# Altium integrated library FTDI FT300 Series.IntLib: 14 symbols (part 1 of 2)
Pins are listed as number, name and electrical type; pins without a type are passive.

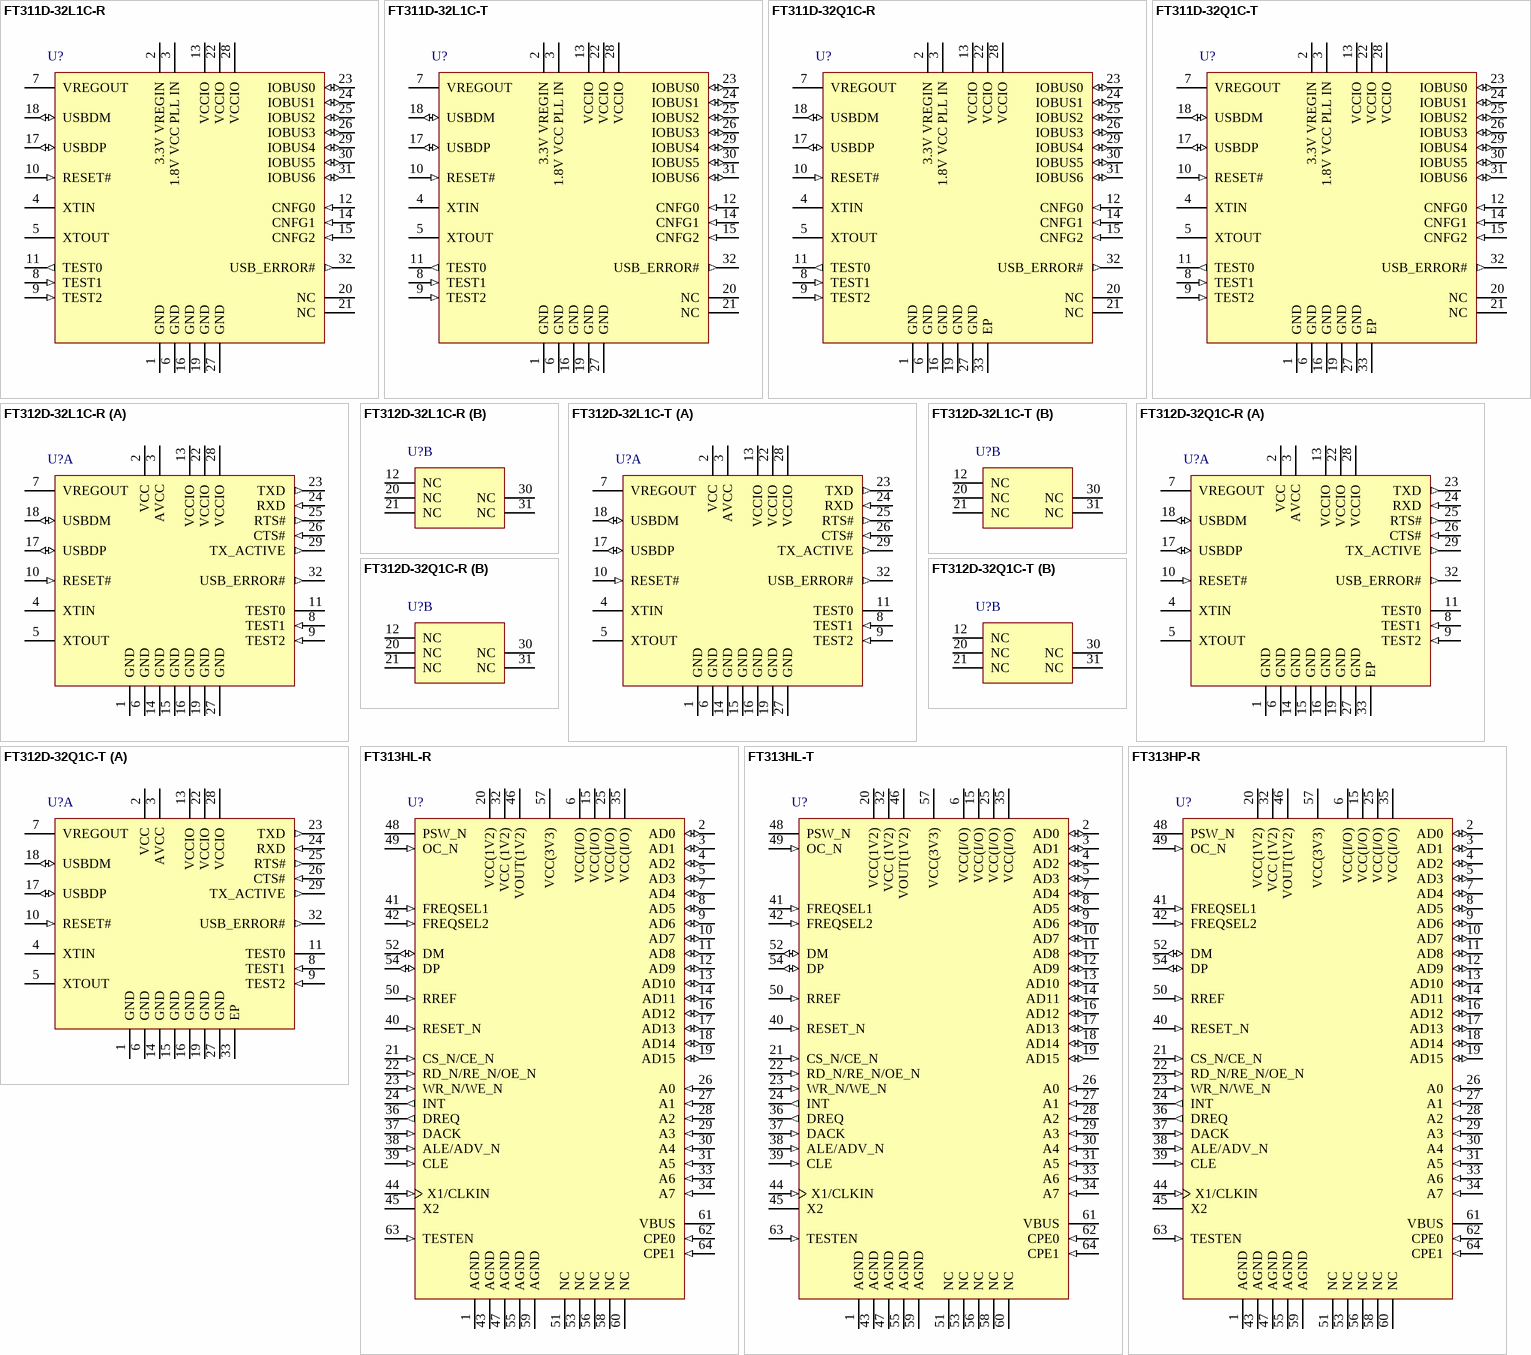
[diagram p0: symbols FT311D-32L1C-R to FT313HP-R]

## FT311D-32L1C-R
designator U?
FT311D Single Chip USB Android Host IC, -40 to +85 degC, 32-pin LQFP, Pb-Free, Tape and Reel; Manufacturer: FTDI; PartNumber: FT311D-32L1C-R
footprint LQFP-32_N (Thin QFP, 32-Leads, Body 7x7mm, Pitch 0.8mm, IPC Medium Density)
footprint LQFP-32_L (Thin QFP, 32-Leads, Body 7x7mm, Pitch 0.8mm, IPC High Density)
footprint LQFP-32_M (Thin QFP, 32-Leads, Body 7x7mm, Pitch 0.8mm, IPC Low Density)
pins: 1 GND (power) "0V Ground input.", 2 3.3V VREGIN (power) "3V3 supply to IC internal 1V8 regulator", 3 1.8V VCC PLL IN (power) "1V8 supply to IC core", 4 XTIN "Input to 12MHz Oscillator Cell. Connect 12MHz crystal across pins 4 and 5.", 5 XTOUT "Output from 12MHz Oscillator Cell. Connect 12MHz crystal across pins 4 and 5.", 6 GND (power) "0V Ground input.", 7 VREGOUT (power) "1V8 output. May be used as input source for pin 3.", 8 TEST1 (in) "For internal use. Pull to GND", 9 TEST2 (in) "For factory use. Pull to 3V3.", 10 RESET# (in) "Reset input (active low).", 11 TEST0 (out) "Active low signal that may be used to control a switch for enabling power to the USB port pin 1 (VBUS).", 12 CNFG0 (in) "Configuration pin 0 used to select between GPIO,UART,PWM,I2C and SPI. Pull to Ground = Logic '0'(No external resistor needed) Leave Open = Logic '1' (Internal Pull up is present)", 13 VCCIO (power) "3V3 supply for the IO cells", 14 CNFG1 (in) "Configuration pin 1 used to select between GPIO,UART,PWM,I2C and SPI. Pull to Ground = Logic '0'(No external resistor needed) Leave Open = Logic '1' (Internal Pull up is present)", 15 CNFG2 (in) "Configuration pin 2 used to select between GPIO,UART,PWM,I2C and SPI. Pull to Ground = Logic '0'(No external resistor needed) Leave Open = Logic '1' (Internal Pull up is present)", 16 GND (power) "0V Ground input.", 17 USBDP (io) "USB Data Signal Plus.", 18 USBDM (io) "USB Data Signal Minus.", 19 GND (power) "0V Ground input.", 20 NC "No connect pins. Leave unterminated.", 21 NC "No connect pins. Leave unterminated.", 22 VCCIO (power) "3V3 supply for the IO cells", 23 IOBUS0 (io) "I/O signal. Function depends on CNFG pin setting.", 24 IOBUS1 (io) "I/O signal. Function depends on CNFG pin setting.", 25 IOBUS2 (io) "I/O signal. Function depends on CNFG pin setting.", 26 IOBUS3 (io) "I/O signal. Function depends on CNFG pin setting.", 27 GND (power) "0V Ground input.", 28 VCCIO (power) "3V3 supply for the IO cells", 29 IOBUS4 (io) "I/O signal. Function depends on CNFG pin setting.", 30 IOBUS5 (io) "I/O signal. Function depends on CNFG pin setting.", 31 IOBUS6 (io) "I/O signal. Function depends on CNFG pin setting.", 32 USB_ERROR# (out) "Output signal to indicate a problem with the USB connection"

## FT311D-32L1C-T
designator U?
FT311D Single Chip USB Android Host IC, -40 to +85 degC, 32-pin LQFP, Pb-Free, Tray; Manufacturer: FTDI; PartNumber: FT311D-32L1C-T
footprint LQFP-32_N (Thin QFP, 32-Leads, Body 7x7mm, Pitch 0.8mm, IPC Medium Density)
footprint LQFP-32_L (Thin QFP, 32-Leads, Body 7x7mm, Pitch 0.8mm, IPC High Density)
footprint LQFP-32_M (Thin QFP, 32-Leads, Body 7x7mm, Pitch 0.8mm, IPC Low Density)
pins: 1 GND (power) "0V Ground input.", 2 3.3V VREGIN (power) "3V3 supply to IC internal 1V8 regulator", 3 1.8V VCC PLL IN (power) "1V8 supply to IC core", 4 XTIN "Input to 12MHz Oscillator Cell. Connect 12MHz crystal across pins 4 and 5.", 5 XTOUT "Output from 12MHz Oscillator Cell. Connect 12MHz crystal across pins 4 and 5.", 6 GND (power) "0V Ground input.", 7 VREGOUT (power) "1V8 output. May be used as input source for pin 3.", 8 TEST1 (in) "For internal use. Pull to GND", 9 TEST2 (in) "For factory use. Pull to 3V3.", 10 RESET# (in) "Reset input (active low).", 11 TEST0 (out) "Active low signal that may be used to control a switch for enabling power to the USB port pin 1 (VBUS).", 12 CNFG0 (in) "Configuration pin 0 used to select between GPIO,UART,PWM,I2C and SPI. Pull to Ground = Logic '0'(No external resistor needed) Leave Open = Logic '1' (Internal Pull up is present)", 13 VCCIO (power) "3V3 supply for the IO cells", 14 CNFG1 (in) "Configuration pin 1 used to select between GPIO,UART,PWM,I2C and SPI. Pull to Ground = Logic '0'(No external resistor needed) Leave Open = Logic '1' (Internal Pull up is present)", 15 CNFG2 (in) "Configuration pin 2 used to select between GPIO,UART,PWM,I2C and SPI. Pull to Ground = Logic '0'(No external resistor needed) Leave Open = Logic '1' (Internal Pull up is present)", 16 GND (power) "0V Ground input.", 17 USBDP (io) "USB Data Signal Plus.", 18 USBDM (io) "USB Data Signal Minus.", 19 GND (power) "0V Ground input.", 20 NC "No connect pins. Leave unterminated.", 21 NC "No connect pins. Leave unterminated.", 22 VCCIO (power) "3V3 supply for the IO cells", 23 IOBUS0 (io) "I/O signal. Function depends on CNFG pin setting.", 24 IOBUS1 (io) "I/O signal. Function depends on CNFG pin setting.", 25 IOBUS2 (io) "I/O signal. Function depends on CNFG pin setting.", 26 IOBUS3 (io) "I/O signal. Function depends on CNFG pin setting.", 27 GND (power) "0V Ground input.", 28 VCCIO (power) "3V3 supply for the IO cells", 29 IOBUS4 (io) "I/O signal. Function depends on CNFG pin setting.", 30 IOBUS5 (io) "I/O signal. Function depends on CNFG pin setting.", 31 IOBUS6 (io) "I/O signal. Function depends on CNFG pin setting.", 32 USB_ERROR# (out) "Output signal to indicate a problem with the USB connection"

## FT311D-32Q1C-R
designator U?
FT311D Single Chip USB Android Host IC, -40 to +85 degC, 32-pin QFN, Pb-Free, Tape and Reel; Manufacturer: FTDI; PartNumber: FT311D-32Q1C-R
footprint QFN7X7-32_N (QFN, 32-Leads, Body 7x7mm, Pitch 0.65mm, Thermal Pad 4.8x4.8mm, IPC Medium Density)
footprint QFN7X7-32_L (QFN, 32-Leads, Body 7x7mm, Pitch 0.65mm, Thermal Pad 4.8x4.8mm, IPC High Density)
footprint QFN7X7-32_M (QFN, 32-Leads, Body 7x7mm, Pitch 0.65mm, Thermal Pad 4.8x4.8mm, IPC Low Density)
pins: 1 GND (power) "0V Ground input.", 2 3.3V VREGIN (power) "3V3 supply to IC internal 1V8 regulator", 3 1.8V VCC PLL IN (power) "1V8 supply to IC core", 4 XTIN "Input to 12MHz Oscillator Cell. Connect 12MHz crystal across pins 4 and 5.", 5 XTOUT "Output from 12MHz Oscillator Cell. Connect 12MHz crystal across pins 4 and 5.", 6 GND (power) "0V Ground input.", 7 VREGOUT (power) "1V8 output. May be used as input source for pin 3.", 8 TEST1 (in) "For internal use. Pull to GND", 9 TEST2 (in) "For factory use. Pull to 3V3.", 10 RESET# (in) "Reset input (active low).", 11 TEST0 (out) "Active low signal that may be used to control a switch for enabling power to the USB port pin 1 (VBUS).", 12 CNFG0 (in) "Configuration pin 0 used to select between GPIO,UART,PWM,I2C and SPI. Pull to Ground = Logic '0'(No external resistor needed) Leave Open = Logic '1' (Internal Pull up is present)", 13 VCCIO (power) "3V3 supply for the IO cells", 14 CNFG1 (in) "Configuration pin 1 used to select between GPIO,UART,PWM,I2C and SPI. Pull to Ground = Logic '0'(No external resistor needed) Leave Open = Logic '1' (Internal Pull up is present)", 15 CNFG2 (in) "Configuration pin 2 used to select between GPIO,UART,PWM,I2C and SPI. Pull to Ground = Logic '0'(No external resistor needed) Leave Open = Logic '1' (Internal Pull up is present)", 16 GND (power) "0V Ground input.", 17 USBDP (io) "USB Data Signal Plus.", 18 USBDM (io) "USB Data Signal Minus.", 19 GND (power) "0V Ground input.", 20 NC "No connect pins. Leave unterminated.", 21 NC "No connect pins. Leave unterminated.", 22 VCCIO (power) "3V3 supply for the IO cells", 23 IOBUS0 (io) "I/O signal. Function depends on CNFG pin setting.", 24 IOBUS1 (io) "I/O signal. Function depends on CNFG pin setting.", 25 IOBUS2 (io) "I/O signal. Function depends on CNFG pin setting.", 26 IOBUS3 (io) "I/O signal. Function depends on CNFG pin setting.", 27 GND (power) "0V Ground input.", 28 VCCIO (power) "3V3 supply for the IO cells", 29 IOBUS4 (io) "I/O signal. Function depends on CNFG pin setting.", 30 IOBUS5 (io) "I/O signal. Function depends on CNFG pin setting.", 31 IOBUS6 (io) "I/O signal. Function depends on CNFG pin setting.", 32 USB_ERROR# (out) "Output signal to indicate a problem with the USB connection", 33 EP (power) "The centre pad should be connected to the GND plane for improved thermal conduction and noise immunity."

## FT311D-32Q1C-T
designator U?
FT311D Single Chip USB Android Host IC, -40 to +85 degC, 32-pin QFN, Pb-Free, Tray; Manufacturer: FTDI; PartNumber: FT311D-32Q1C-T
footprint QFN7X7-32_N (QFN, 32-Leads, Body 7x7mm, Pitch 0.65mm, Thermal Pad 4.8x4.8mm, IPC Medium Density)
footprint QFN7X7-32_L (QFN, 32-Leads, Body 7x7mm, Pitch 0.65mm, Thermal Pad 4.8x4.8mm, IPC High Density)
footprint QFN7X7-32_M (QFN, 32-Leads, Body 7x7mm, Pitch 0.65mm, Thermal Pad 4.8x4.8mm, IPC Low Density)
pins: 1 GND (power) "0V Ground input.", 2 3.3V VREGIN (power) "3V3 supply to IC internal 1V8 regulator", 3 1.8V VCC PLL IN (power) "1V8 supply to IC core", 4 XTIN "Input to 12MHz Oscillator Cell. Connect 12MHz crystal across pins 4 and 5.", 5 XTOUT "Output from 12MHz Oscillator Cell. Connect 12MHz crystal across pins 4 and 5.", 6 GND (power) "0V Ground input.", 7 VREGOUT (power) "1V8 output. May be used as input source for pin 3.", 8 TEST1 (in) "For internal use. Pull to GND", 9 TEST2 (in) "For factory use. Pull to 3V3.", 10 RESET# (in) "Reset input (active low).", 11 TEST0 (out) "Active low signal that may be used to control a switch for enabling power to the USB port pin 1 (VBUS).", 12 CNFG0 (in) "Configuration pin 0 used to select between GPIO,UART,PWM,I2C and SPI. Pull to Ground = Logic '0'(No external resistor needed) Leave Open = Logic '1' (Internal Pull up is present)", 13 VCCIO (power) "3V3 supply for the IO cells", 14 CNFG1 (in) "Configuration pin 1 used to select between GPIO,UART,PWM,I2C and SPI. Pull to Ground = Logic '0'(No external resistor needed) Leave Open = Logic '1' (Internal Pull up is present)", 15 CNFG2 (in) "Configuration pin 2 used to select between GPIO,UART,PWM,I2C and SPI. Pull to Ground = Logic '0'(No external resistor needed) Leave Open = Logic '1' (Internal Pull up is present)", 16 GND (power) "0V Ground input.", 17 USBDP (io) "USB Data Signal Plus.", 18 USBDM (io) "USB Data Signal Minus.", 19 GND (power) "0V Ground input.", 20 NC "No connect pins. Leave unterminated.", 21 NC "No connect pins. Leave unterminated.", 22 VCCIO (power) "3V3 supply for the IO cells", 23 IOBUS0 (io) "I/O signal. Function depends on CNFG pin setting.", 24 IOBUS1 (io) "I/O signal. Function depends on CNFG pin setting.", 25 IOBUS2 (io) "I/O signal. Function depends on CNFG pin setting.", 26 IOBUS3 (io) "I/O signal. Function depends on CNFG pin setting.", 27 GND (power) "0V Ground input.", 28 VCCIO (power) "3V3 supply for the IO cells", 29 IOBUS4 (io) "I/O signal. Function depends on CNFG pin setting.", 30 IOBUS5 (io) "I/O signal. Function depends on CNFG pin setting.", 31 IOBUS6 (io) "I/O signal. Function depends on CNFG pin setting.", 32 USB_ERROR# (out) "Output signal to indicate a problem with the USB connection", 33 EP (power) "The centre pad should be connected to the GND plane for improved thermal conduction and noise immunity."

## FT312D-32L1C-R
designator U?
FT312D Single Chip USB Android Host IC, -40 to +85 degC, 32-pin LQFP, Pb-Free, Tape and Reel; Manufacturer: FTDI; PartNumber: FT312D-32L1C-R
footprint LQFP-32_N (Thin QFP, 32-Leads, Body 7x7mm, Pitch 0.8mm, IPC Medium Density)
footprint LQFP-32_L (Thin QFP, 32-Leads, Body 7x7mm, Pitch 0.8mm, IPC High Density)
footprint LQFP-32_M (Thin QFP, 32-Leads, Body 7x7mm, Pitch 0.8mm, IPC Low Density)
part A pins: 1 GND (power) "0V Ground input.", 2 VCC (power) "3V3 supply to IC internal 1V8 regulator", 3 AVCC (power) "1V8 supply to IC core", 4 XTIN "Input to 12MHz Oscillator Cell. Connect 12MHz crystal across pins 4 and 5.", 5 XTOUT "Output from 12MHz Oscillator Cell. Connect 12MHz crystal across pins 4 and 5.", 6 GND (power) "0V Ground input.", 7 VREGOUT (power) "1V8 output. May be used as input source for pin 3.", 8 TEST1 (in) "For internal use. Pull to GND", 9 TEST2 (in) "For factory use. Pull to 3V3.", 10 RESET# (in) "Reset input (active low).", 11 TEST0 "Leave unterminated.", 13 VCCIO (power) "3V3 supply for the IO cells", 14 GND (power) "0V Ground input.", 15 GND (power) "0V Ground input.", 16 GND (power) "0V Ground input.", 17 USBDP (io) "USB Data Signal Plus.", 18 USBDM (io) "USB Data Signal Minus.", 19 GND (power) "0V Ground input.", 22 VCCIO (power) "3V3 supply for the IO cells", 23 TXD (out) "Transmit asynchronous data output", 24 RXD (in) "Receive asynchronous data input", 25 RTS# (out) "Request to send control output", 26 CTS# (in) "Clear to send control input", 27 GND (power) "0V Ground input.", 28 VCCIO (power) "3V3 supply for the IO cells", 29 TX_ACTIVE (out) "UART active signal (typically used with RS485)", 32 USB_ERROR# (out) "Output signal to indicate a problem with the USB connection"
part B pins: 12 NC "No connect pins. Leave unterminated.", 20 NC "No connect pins. Leave unterminated.", 21 NC "No connect pins. Leave unterminated.", 30 NC "No connect pins. Leave un-terminated", 31 NC "No connect pins. Leave un-terminated"

## FT312D-32L1C-T
designator U?
FT312D Single Chip USB Android Host IC, -40 to +85 degC, 32-pin LQFP, Pb-Free, Tray; Manufacturer: FTDI; PartNumber: FT312D-32L1C-T
footprint LQFP-32_N (Thin QFP, 32-Leads, Body 7x7mm, Pitch 0.8mm, IPC Medium Density)
footprint LQFP-32_L (Thin QFP, 32-Leads, Body 7x7mm, Pitch 0.8mm, IPC High Density)
footprint LQFP-32_M (Thin QFP, 32-Leads, Body 7x7mm, Pitch 0.8mm, IPC Low Density)
part A pins: 1 GND (power) "0V Ground input.", 2 VCC (power) "3V3 supply to IC internal 1V8 regulator", 3 AVCC (power) "1V8 supply to IC core", 4 XTIN "Input to 12MHz Oscillator Cell. Connect 12MHz crystal across pins 4 and 5.", 5 XTOUT "Output from 12MHz Oscillator Cell. Connect 12MHz crystal across pins 4 and 5.", 6 GND (power) "0V Ground input.", 7 VREGOUT (power) "1V8 output. May be used as input source for pin 3.", 8 TEST1 (in) "For internal use. Pull to GND", 9 TEST2 (in) "For factory use. Pull to 3V3.", 10 RESET# (in) "Reset input (active low).", 11 TEST0 "Leave unterminated.", 13 VCCIO (power) "3V3 supply for the IO cells", 14 GND (power) "0V Ground input.", 15 GND (power) "0V Ground input.", 16 GND (power) "0V Ground input.", 17 USBDP (io) "USB Data Signal Plus.", 18 USBDM (io) "USB Data Signal Minus.", 19 GND (power) "0V Ground input.", 22 VCCIO (power) "3V3 supply for the IO cells", 23 TXD (out) "Transmit asynchronous data output", 24 RXD (in) "Receive asynchronous data input", 25 RTS# (out) "Request to send control output", 26 CTS# (in) "Clear to send control input", 27 GND (power) "0V Ground input.", 28 VCCIO (power) "3V3 supply for the IO cells", 29 TX_ACTIVE (out) "UART active signal (typically used with RS485)", 32 USB_ERROR# (out) "Output signal to indicate a problem with the USB connection"
part B pins: 12 NC "No connect pins. Leave unterminated.", 20 NC "No connect pins. Leave unterminated.", 21 NC "No connect pins. Leave unterminated.", 30 NC "No connect pins. Leave un-terminated", 31 NC "No connect pins. Leave un-terminated"

## FT312D-32Q1C-R
designator U?
FT312D Single Chip USB Android Host IC, -40 to +85 degC, 32-pin QFN, Pb-Free, Tape and Reel; Manufacturer: FTDI; PartNumber: FT312D-32Q1C-R
footprint QFN7X7-32_N (QFN, 32-Leads, Body 7x7mm, Pitch 0.65mm, Thermal Pad 4.8x4.8mm, IPC Medium Density)
footprint QFN7X7-32_L (QFN, 32-Leads, Body 7x7mm, Pitch 0.65mm, Thermal Pad 4.8x4.8mm, IPC High Density)
footprint QFN7X7-32_M (QFN, 32-Leads, Body 7x7mm, Pitch 0.65mm, Thermal Pad 4.8x4.8mm, IPC Low Density)
part A pins: 1 GND (power) "0V Ground input.", 2 VCC (power) "3V3 supply to IC internal 1V8 regulator", 3 AVCC (power) "1V8 supply to IC core", 4 XTIN "Input to 12MHz Oscillator Cell. Connect 12MHz crystal across pins 4 and 5.", 5 XTOUT "Output from 12MHz Oscillator Cell. Connect 12MHz crystal across pins 4 and 5.", 6 GND (power) "0V Ground input.", 7 VREGOUT (power) "1V8 output. May be used as input source for pin 3.", 8 TEST1 (in) "For internal use. Pull to GND", 9 TEST2 (in) "For factory use. Pull to 3V3.", 10 RESET# (in) "Reset input (active low).", 11 TEST0 "Leave unterminated.", 13 VCCIO (power) "3V3 supply for the IO cells", 14 GND (power) "0V Ground input.", 15 GND (power) "0V Ground input.", 16 GND (power) "0V Ground input.", 17 USBDP (io) "USB Data Signal Plus.", 18 USBDM (io) "USB Data Signal Minus.", 19 GND (power) "0V Ground input.", 22 VCCIO (power) "3V3 supply for the IO cells", 23 TXD (out) "Transmit asynchronous data output", 24 RXD (in) "Receive asynchronous data input", 25 RTS# (out) "Request to send control output", 26 CTS# (in) "Clear to send control input", 27 GND (power) "0V Ground input.", 28 VCCIO (power) "3V3 supply for the IO cells", 29 TX_ACTIVE (out) "UART active signal (typically used with RS485)", 32 USB_ERROR# (out) "Output signal to indicate a problem with the USB connection", 33 EP (power) "The centre pad should be connected to the GND plane for improved thermal conduction and noise immunity."
part B pins: 12 NC "No connect pins. Leave unterminated.", 20 NC "No connect pins. Leave unterminated.", 21 NC "No connect pins. Leave unterminated.", 30 NC "No connect pins. Leave un-terminated", 31 NC "No connect pins. Leave un-terminated"

## FT312D-32Q1C-T
designator U?
FT312D Single Chip USB Android Host IC, -40 to +85 degC, 32-pin QFN, Pb-Free, Tray; Manufacturer: FTDI; PartNumber: FT312D-32Q1C-T
footprint QFN7X7-32_N (QFN, 32-Leads, Body 7x7mm, Pitch 0.65mm, Thermal Pad 4.8x4.8mm, IPC Medium Density)
footprint QFN7X7-32_L (QFN, 32-Leads, Body 7x7mm, Pitch 0.65mm, Thermal Pad 4.8x4.8mm, IPC High Density)
footprint QFN7X7-32_M (QFN, 32-Leads, Body 7x7mm, Pitch 0.65mm, Thermal Pad 4.8x4.8mm, IPC Low Density)
part A pins: 1 GND (power) "0V Ground input.", 2 VCC (power) "3V3 supply to IC internal 1V8 regulator", 3 AVCC (power) "1V8 supply to IC core", 4 XTIN "Input to 12MHz Oscillator Cell. Connect 12MHz crystal across pins 4 and 5.", 5 XTOUT "Output from 12MHz Oscillator Cell. Connect 12MHz crystal across pins 4 and 5.", 6 GND (power) "0V Ground input.", 7 VREGOUT (power) "1V8 output. May be used as input source for pin 3.", 8 TEST1 (in) "For internal use. Pull to GND", 9 TEST2 (in) "For factory use. Pull to 3V3.", 10 RESET# (in) "Reset input (active low).", 11 TEST0 "Leave unterminated.", 13 VCCIO (power) "3V3 supply for the IO cells", 14 GND (power) "0V Ground input.", 15 GND (power) "0V Ground input.", 16 GND (power) "0V Ground input.", 17 USBDP (io) "USB Data Signal Plus.", 18 USBDM (io) "USB Data Signal Minus.", 19 GND (power) "0V Ground input.", 22 VCCIO (power) "3V3 supply for the IO cells", 23 TXD (out) "Transmit asynchronous data output", 24 RXD (in) "Receive asynchronous data input", 25 RTS# (out) "Request to send control output", 26 CTS# (in) "Clear to send control input", 27 GND (power) "0V Ground input.", 28 VCCIO (power) "3V3 supply for the IO cells", 29 TX_ACTIVE (out) "UART active signal (typically used with RS485)", 32 USB_ERROR# (out) "Output signal to indicate a problem with the USB connection", 33 EP (power) "The centre pad should be connected to the GND plane for improved thermal conduction and noise immunity."
part B pins: 12 NC "No connect pins. Leave unterminated.", 20 NC "No connect pins. Leave unterminated.", 21 NC "No connect pins. Leave unterminated.", 30 NC "No connect pins. Leave un-terminated", 31 NC "No connect pins. Leave un-terminated"

## FT313HL-R
designator U?
FT313H Single Chip USB2.0 HS Embedded Host Controller, -40 to +85 degC, 64-pin LQFP, Pb-Free, Tape and Reel; Manufacturer: FTDI; PartNumber: FT313HL-R
footprint LQFP-64_N (Thin QFP, 64-Leads, Body 10x10mm, Pitch 0.5mm, IPC Medium Density)
footprint LQFP-64_L (Thin QFP, 64-Leads, Body 10x10mm, Pitch 0.5mm, IPC High Density)
footprint LQFP-64_M (Thin QFP, 64-Leads, Body 10x10mm, Pitch 0.5mm, IPC Low Density)
pins: 1 AGND (power) "Analog Ground", 2 AD0 (io) "Bit 0 of the address and data bus. Bidirectional pad; push-pull, three-state output. 3.3V tolerant", 3 AD1 (io) "Bit 1 of the address and data bus. Bidirectional pad; push-pull, three-state output. 3.3V tolerant", 4 AD2 (io) "Bit 2 of the address and data bus. Bidirectional pad; push-pull, three-state output. 3.3V tolerant", 5 AD3 (io) "Bit 3 of the address and data bus. Bidirectional pad; push-pull, three-state output. 3.3V tolerant", 6 VCC(I/O) (power) "I/O supply voltage; connect a 0.1uF decoupling capacitor. 1.8V, 2.5V or 3.3V", 7 AD4 (io) "Bit 4 of the address and data bus. Bidirectional pad; push-pull, three-state output. 3.3V tolerant", 8 AD5 (io) "Bit 5 of the address and data bus. Bidirectional pad; push-pull, three-state output. 3.3V tolerant", 9 AD6 (io) "Bit 6 of the address and data bus. Bidirectional pad; push-pull, three-state output. 3.3V tolerant", 10 AD7 (io) "Bit 7 of the address and data bus. Bidirectional pad; push-pull, three-state output. 3.3V tolerant", 11 AD8 (io) "Bit 8 of the address and data bus. Bidirectional pad; push-pull, three-state output. 3.3V tolerant", 12 AD9 (io) "Bit 9 of the address and data bus. Bidirectional pad; push-pull, three-state output. 3.3V tolerant", 13 AD10 (io) "Bit 10 of the address and data bus. Bidirectional pad; push-pull, three-state output. 3.3V tolerant", 14 AD11 (io) "Bit 11 of the address and data bus. Bidirectional pad; push-pull, three-state output. 3.3V tolerant", 15 VCC(I/O) (power) "I/O supply voltage; connect a 0.1uF decoupling capacitor. 1.8V, 2.5V or 3.3V", 16 AD12 (io) "Bit 12 of the address and data bus. Bidirectional pad; push-pull, three-state output. 3.3V tolerant", 17 AD13 (io) "Bit 13 of the address and data bus. Bidirectional pad; push-pull, three-state output. 3.3V tolerant", 18 AD14 (io) "Bit 14 of the address and data bus. Bidirectional pad; push-pull, three-state output. 3.3V tolerant", 19 AD15 (io) "Bit 15 of the address and data bus. Bidirectional pad; push-pull, three-state output. 3.3V tolerant", 20 VCC(1V2) (power) "Core power 1.2V input; for normal operation, this pin must be connected to pin 46. Connect a 0.1uF decoupling capacitor", 21 CS_N/CE_N (in), 22 RD_N/RE_N/OE_N (in), 23 WR_N/WE_N (in), 24 INT (out) "Interrupt output. Push-pull output; 3.3V tolerant", 25 VCC(I/O) (power) "I/O supply voltage; connect a 0.1uF decoupling capacitor. 1.8V, 2.5V or 3.3V", 26 A0 (in) "Bit 0 of the address bus; when not in use, connect to GND. Input; 3.3V tolerant", 27 A1 (in) "Bit 1 of the address bus; when not in use, connect to GND. Input; 3.3V tolerant", 28 A2 (in) "Bit 2 of the address bus; when not in use, connect to GND. Input; 3.3V tolerant", 29 A3 (in) "Bit 3 of the address bus; when not in use, connect to GND. Input; 3.3V tolerant", 30 A4 (in) "Bit 4 of the address bus; when not in use, connect to GND. Input; 3.3V tolerant", 31 A5 (in) "Bit 5 of the address bus; when not in use, connect to GND. Input; 3.3V tolerant", 32 VCC (1V2) (power) "Core power 1.2V input; for normal operation, this pin must be connected to pin 46. Connect a 0.1uF decoupling capacitor.", 33 A6 (in) "Bit 6 of the address bus; when not in use, connect to GND. Input; 3.3V tolerant", 34 A7 (in) "Bit 7 of the address bus; when not in use, connect to GND. Input; 3.3V tolerant", 35 VCC(I/O) (power) "I/O supply voltage; connect a 0.1uF decoupling capacitor. 1.8V, 2.5V or 3.3V", 36 DREQ (out) "DMA request; Push-pull output; 3.3V tolerant", 37 DACK (in) "DMA acknowledge; Internal pull-down. Input; 3.3V tolerant", 38 ALE/ADV_N (in), 39 CLE (in) "Command latch enable. Input; 3.3V tolerant", 40 RESET_N (in) "Chip reset; Internal pull-up. Input; 3.3V tolerant", 41 FREQSEL1 (in) "Input clock frequency selection pin1. Input; 3.3V tolerant", 42 FREQSEL2 (in) "Input clock frequency selection pin2. Input; 3.3V tolerant", 43 AGND (power) "Analog Ground", 44 X1/CLKIN (in) "Crystal oscillator or clock input; 3.3V peak input allowed", 45 X2 "Crystal oscillator output; leave open if an external clock is applied on pin X1/CLKIN", 46 VOUT(1V2) (power) "Internal 1.2V regulator output; connect 4.7uF and 0.1uF decoupling capacitors to this pin.", 47 AGND (power) "Analog Ground", 48 PSW_N (oc) "Port power switch; when not in use, connect to VCC(3V3) through a 10kOhm resistor. Open drain output; 5V tolerant", 49 OC_N (in) "Over current input; when not in use, connect to VCC(3V3) through a 10KOhm resistor. Input; 5V tolerant", 50 RREF (in) "Port reference resistor connection. Connect 12 kOhm±1% resistor between RREF and GND", 51 NC "No connect", 52 DM (io) "Port DM; connect to the D- pin of the USB connector", 53 NC "No connect", 54 DP (io) "Port DP; connect to the D+ pin of the USB connector", 55 AGND (power) "Analog Ground", 56 NC "No connect", 57 VCC(3V3) (power) "Supply 3.3V voltage; Connect 10uF and 0.1uF decoupling capacitors", 58 NC "No connect", 59 AGND (power) "Analog Ground", 60 NC "No connect", 61 VBUS (power) "VBUS discharge. 5V tolerant", 62 CPE0 (in) "Bit 0 to select charging port emulation type", 63 TESTEN (in) "Enable test mode. Internal pull-down. For normal operation leave floating.", 64 CPE1 (in) "Bit 1 to select charging port emulation type"

## FT313HL-T
designator U?
FT313H Single Chip USB2.0 HS Embedded Host Controller, -40 to +85 degC, 64-pin LQFP, Pb-Free, Tray; Manufacturer: FTDI; PartNumber: FT313HL-T
footprint LQFP-64_N (Thin QFP, 64-Leads, Body 10x10mm, Pitch 0.5mm, IPC Medium Density)
footprint LQFP-64_L (Thin QFP, 64-Leads, Body 10x10mm, Pitch 0.5mm, IPC High Density)
footprint LQFP-64_M (Thin QFP, 64-Leads, Body 10x10mm, Pitch 0.5mm, IPC Low Density)
pins: 1 AGND (power) "Analog Ground", 2 AD0 (io) "Bit 0 of the address and data bus. Bidirectional pad; push-pull, three-state output. 3.3V tolerant", 3 AD1 (io) "Bit 1 of the address and data bus. Bidirectional pad; push-pull, three-state output. 3.3V tolerant", 4 AD2 (io) "Bit 2 of the address and data bus. Bidirectional pad; push-pull, three-state output. 3.3V tolerant", 5 AD3 (io) "Bit 3 of the address and data bus. Bidirectional pad; push-pull, three-state output. 3.3V tolerant", 6 VCC(I/O) (power) "I/O supply voltage; connect a 0.1uF decoupling capacitor. 1.8V, 2.5V or 3.3V", 7 AD4 (io) "Bit 4 of the address and data bus. Bidirectional pad; push-pull, three-state output. 3.3V tolerant", 8 AD5 (io) "Bit 5 of the address and data bus. Bidirectional pad; push-pull, three-state output. 3.3V tolerant", 9 AD6 (io) "Bit 6 of the address and data bus. Bidirectional pad; push-pull, three-state output. 3.3V tolerant", 10 AD7 (io) "Bit 7 of the address and data bus. Bidirectional pad; push-pull, three-state output. 3.3V tolerant", 11 AD8 (io) "Bit 8 of the address and data bus. Bidirectional pad; push-pull, three-state output. 3.3V tolerant", 12 AD9 (io) "Bit 9 of the address and data bus. Bidirectional pad; push-pull, three-state output. 3.3V tolerant", 13 AD10 (io) "Bit 10 of the address and data bus. Bidirectional pad; push-pull, three-state output. 3.3V tolerant", 14 AD11 (io) "Bit 11 of the address and data bus. Bidirectional pad; push-pull, three-state output. 3.3V tolerant", 15 VCC(I/O) (power) "I/O supply voltage; connect a 0.1uF decoupling capacitor. 1.8V, 2.5V or 3.3V", 16 AD12 (io) "Bit 12 of the address and data bus. Bidirectional pad; push-pull, three-state output. 3.3V tolerant", 17 AD13 (io) "Bit 13 of the address and data bus. Bidirectional pad; push-pull, three-state output. 3.3V tolerant", 18 AD14 (io) "Bit 14 of the address and data bus. Bidirectional pad; push-pull, three-state output. 3.3V tolerant", 19 AD15 (io) "Bit 15 of the address and data bus. Bidirectional pad; push-pull, three-state output. 3.3V tolerant", 20 VCC(1V2) (power) "Core power 1.2V input; for normal operation, this pin must be connected to pin 46. Connect a 0.1uF decoupling capacitor", 21 CS_N/CE_N (in), 22 RD_N/RE_N/OE_N (in), 23 WR_N/WE_N (in), 24 INT (out) "Interrupt output. Push-pull output; 3.3V tolerant", 25 VCC(I/O) (power) "I/O supply voltage; connect a 0.1uF decoupling capacitor. 1.8V, 2.5V or 3.3V", 26 A0 (in) "Bit 0 of the address bus; when not in use, connect to GND. Input; 3.3V tolerant", 27 A1 (in) "Bit 1 of the address bus; when not in use, connect to GND. Input; 3.3V tolerant", 28 A2 (in) "Bit 2 of the address bus; when not in use, connect to GND. Input; 3.3V tolerant", 29 A3 (in) "Bit 3 of the address bus; when not in use, connect to GND. Input; 3.3V tolerant", 30 A4 (in) "Bit 4 of the address bus; when not in use, connect to GND. Input; 3.3V tolerant", 31 A5 (in) "Bit 5 of the address bus; when not in use, connect to GND. Input; 3.3V tolerant", 32 VCC (1V2) (power) "Core power 1.2V input; for normal operation, this pin must be connected to pin 46. Connect a 0.1uF decoupling capacitor.", 33 A6 (in) "Bit 6 of the address bus; when not in use, connect to GND. Input; 3.3V tolerant", 34 A7 (in) "Bit 7 of the address bus; when not in use, connect to GND. Input; 3.3V tolerant", 35 VCC(I/O) (power) "I/O supply voltage; connect a 0.1uF decoupling capacitor. 1.8V, 2.5V or 3.3V", 36 DREQ (out) "DMA request; Push-pull output; 3.3V tolerant", 37 DACK (in) "DMA acknowledge; Internal pull-down. Input; 3.3V tolerant", 38 ALE/ADV_N (in), 39 CLE (in) "Command latch enable. Input; 3.3V tolerant", 40 RESET_N (in) "Chip reset; Internal pull-up. Input; 3.3V tolerant", 41 FREQSEL1 (in) "Input clock frequency selection pin1. Input; 3.3V tolerant", 42 FREQSEL2 (in) "Input clock frequency selection pin2. Input; 3.3V tolerant", 43 AGND (power) "Analog Ground", 44 X1/CLKIN (in) "Crystal oscillator or clock input; 3.3V peak input allowed", 45 X2 "Crystal oscillator output; leave open if an external clock is applied on pin X1/CLKIN", 46 VOUT(1V2) (power) "Internal 1.2V regulator output; connect 4.7uF and 0.1uF decoupling capacitors to this pin.", 47 AGND (power) "Analog Ground", 48 PSW_N (oc) "Port power switch; when not in use, connect to VCC(3V3) through a 10kOhm resistor. Open drain output; 5V tolerant", 49 OC_N (in) "Over current input; when not in use, connect to VCC(3V3) through a 10KOhm resistor. Input; 5V tolerant", 50 RREF (in) "Port reference resistor connection. Connect 12 kOhm±1% resistor between RREF and GND", 51 NC "No connect", 52 DM (io) "Port DM; connect to the D- pin of the USB connector", 53 NC "No connect", 54 DP (io) "Port DP; connect to the D+ pin of the USB connector", 55 AGND (power) "Analog Ground", 56 NC "No connect", 57 VCC(3V3) (power) "Supply 3.3V voltage; Connect 10uF and 0.1uF decoupling capacitors", 58 NC "No connect", 59 AGND (power) "Analog Ground", 60 NC "No connect", 61 VBUS (power) "VBUS discharge. 5V tolerant", 62 CPE0 (in) "Bit 0 to select charging port emulation type", 63 TESTEN (in) "Enable test mode. Internal pull-down. For normal operation leave floating.", 64 CPE1 (in) "Bit 1 to select charging port emulation type"

## FT313HP-R
designator U?
FT313H Single Chip USB2.0 HS Embedded Host Controller, -40 to +85 degC, 64-pin TQFP, Pb-Free, Tape and Reel; Manufacturer: FTDI; PartNumber: FT313HP-R
footprint TQFP-64_N (QFP, 64-Leads, Body 7x7mm,Pitch 0.4mm, IPC Medium Density)
footprint TQFP-64_L (QFP, 64-Leads, Body 7x7mm,Pitch 0.4mm, IPC High Density)
footprint TQFP-64_M (QFP, 64-Leads, Body 7x7mm, Pitch 0.4mm, IPC Low Density)
pins: 1 AGND (power) "Analog Ground", 2 AD0 (io) "Bit 0 of the address and data bus. Bidirectional pad; push-pull, three-state output. 3.3V tolerant", 3 AD1 (io) "Bit 1 of the address and data bus. Bidirectional pad; push-pull, three-state output. 3.3V tolerant", 4 AD2 (io) "Bit 2 of the address and data bus. Bidirectional pad; push-pull, three-state output. 3.3V tolerant", 5 AD3 (io) "Bit 3 of the address and data bus. Bidirectional pad; push-pull, three-state output. 3.3V tolerant", 6 VCC(I/O) (power) "I/O supply voltage; connect a 0.1uF decoupling capacitor. 1.8V, 2.5V or 3.3V", 7 AD4 (io) "Bit 4 of the address and data bus. Bidirectional pad; push-pull, three-state output. 3.3V tolerant", 8 AD5 (io) "Bit 5 of the address and data bus. Bidirectional pad; push-pull, three-state output. 3.3V tolerant", 9 AD6 (io) "Bit 6 of the address and data bus. Bidirectional pad; push-pull, three-state output. 3.3V tolerant", 10 AD7 (io) "Bit 7 of the address and data bus. Bidirectional pad; push-pull, three-state output. 3.3V tolerant", 11 AD8 (io) "Bit 8 of the address and data bus. Bidirectional pad; push-pull, three-state output. 3.3V tolerant", 12 AD9 (io) "Bit 9 of the address and data bus. Bidirectional pad; push-pull, three-state output. 3.3V tolerant", 13 AD10 (io) "Bit 10 of the address and data bus. Bidirectional pad; push-pull, three-state output. 3.3V tolerant", 14 AD11 (io) "Bit 11 of the address and data bus. Bidirectional pad; push-pull, three-state output. 3.3V tolerant", 15 VCC(I/O) (power) "I/O supply voltage; connect a 0.1uF decoupling capacitor. 1.8V, 2.5V or 3.3V", 16 AD12 (io) "Bit 12 of the address and data bus. Bidirectional pad; push-pull, three-state output. 3.3V tolerant", 17 AD13 (io) "Bit 13 of the address and data bus. Bidirectional pad; push-pull, three-state output. 3.3V tolerant", 18 AD14 (io) "Bit 14 of the address and data bus. Bidirectional pad; push-pull, three-state output. 3.3V tolerant", 19 AD15 (io) "Bit 15 of the address and data bus. Bidirectional pad; push-pull, three-state output. 3.3V tolerant", 20 VCC(1V2) (power) "Core power 1.2V input; for normal operation, this pin must be connected to pin 46. Connect a 0.1uF decoupling capacitor", 21 CS_N/CE_N (in), 22 RD_N/RE_N/OE_N (in), 23 WR_N/WE_N (in), 24 INT (out) "Interrupt output. Push-pull output; 3.3V tolerant", 25 VCC(I/O) (power) "I/O supply voltage; connect a 0.1uF decoupling capacitor. 1.8V, 2.5V or 3.3V", 26 A0 (in) "Bit 0 of the address bus; when not in use, connect to GND. Input; 3.3V tolerant", 27 A1 (in) "Bit 1 of the address bus; when not in use, connect to GND. Input; 3.3V tolerant", 28 A2 (in) "Bit 2 of the address bus; when not in use, connect to GND. Input; 3.3V tolerant", 29 A3 (in) "Bit 3 of the address bus; when not in use, connect to GND. Input; 3.3V tolerant", 30 A4 (in) "Bit 4 of the address bus; when not in use, connect to GND. Input; 3.3V tolerant", 31 A5 (in) "Bit 5 of the address bus; when not in use, connect to GND. Input; 3.3V tolerant", 32 VCC (1V2) (power) "Core power 1.2V input; for normal operation, this pin must be connected to pin 46. Connect a 0.1uF decoupling capacitor.", 33 A6 (in) "Bit 6 of the address bus; when not in use, connect to GND. Input; 3.3V tolerant", 34 A7 (in) "Bit 7 of the address bus; when not in use, connect to GND. Input; 3.3V tolerant", 35 VCC(I/O) (power) "I/O supply voltage; connect a 0.1uF decoupling capacitor. 1.8V, 2.5V or 3.3V", 36 DREQ (out) "DMA request; Push-pull output; 3.3V tolerant", 37 DACK (in) "DMA acknowledge; Internal pull-down. Input; 3.3V tolerant", 38 ALE/ADV_N (in), 39 CLE (in) "Command latch enable. Input; 3.3V tolerant", 40 RESET_N (in) "Chip reset; Internal pull-up. Input; 3.3V tolerant", 41 FREQSEL1 (in) "Input clock frequency selection pin1. Input; 3.3V tolerant", 42 FREQSEL2 (in) "Input clock frequency selection pin2. Input; 3.3V tolerant", 43 AGND (power) "Analog Ground", 44 X1/CLKIN (in) "Crystal oscillator or clock input; 3.3V peak input allowed", 45 X2 "Crystal oscillator output; leave open if an external clock is applied on pin X1/CLKIN", 46 VOUT(1V2) (power) "Internal 1.2V regulator output; connect 4.7uF and 0.1uF decoupling capacitors to this pin.", 47 AGND (power) "Analog Ground", 48 PSW_N (oc) "Port power switch; when not in use, connect to VCC(3V3) through a 10kOhm resistor. Open drain output; 5V tolerant", 49 OC_N (in) "Over current input; when not in use, connect to VCC(3V3) through a 10KOhm resistor. Input; 5V tolerant", 50 RREF (in) "Port reference resistor connection. Connect 12 kOhm±1% resistor between RREF and GND", 51 NC "No connect", 52 DM (io) "Port DM; connect to the D- pin of the USB connector", 53 NC "No connect", 54 DP (io) "Port DP; connect to the D+ pin of the USB connector", 55 AGND (power) "Analog Ground", 56 NC "No connect", 57 VCC(3V3) (power) "Supply 3.3V voltage; Connect 10uF and 0.1uF decoupling capacitors", 58 NC "No connect", 59 AGND (power) "Analog Ground", 60 NC "No connect", 61 VBUS (power) "VBUS discharge. 5V tolerant", 62 CPE0 (in) "Bit 0 to select charging port emulation type", 63 TESTEN (in) "Enable test mode. Internal pull-down. For normal operation leave floating.", 64 CPE1 (in) "Bit 1 to select charging port emulation type"

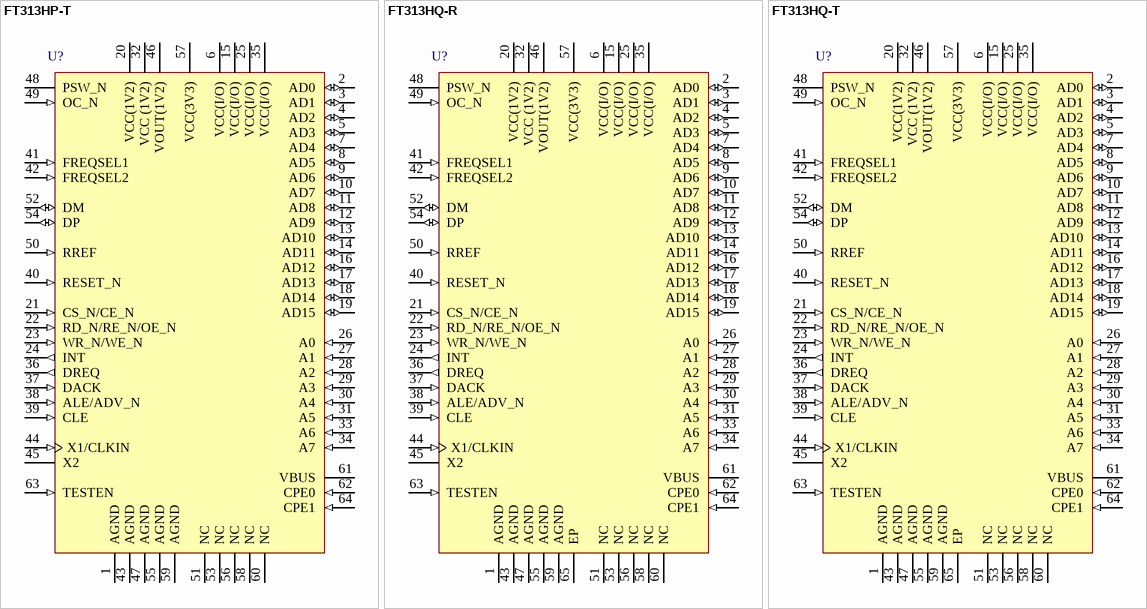
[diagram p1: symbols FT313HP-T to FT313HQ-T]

## FT313HP-T
designator U?
FT313H Single Chip USB2.0 HS Embedded Host Controller, -40 to +85 degC, 64-pin TQFP, Pb-Free, Tray; Manufacturer: FTDI; PartNumber: FT313HP-T
footprint TQFP-64_N (QFP, 64-Leads, Body 7x7mm,Pitch 0.4mm, IPC Medium Density)
footprint TQFP-64_L (QFP, 64-Leads, Body 7x7mm,Pitch 0.4mm, IPC High Density)
footprint TQFP-64_M (QFP, 64-Leads, Body 7x7mm, Pitch 0.4mm, IPC Low Density)
pins: 1 AGND (power) "Analog Ground", 2 AD0 (io) "Bit 0 of the address and data bus. Bidirectional pad; push-pull, three-state output. 3.3V tolerant", 3 AD1 (io) "Bit 1 of the address and data bus. Bidirectional pad; push-pull, three-state output. 3.3V tolerant", 4 AD2 (io) "Bit 2 of the address and data bus. Bidirectional pad; push-pull, three-state output. 3.3V tolerant", 5 AD3 (io) "Bit 3 of the address and data bus. Bidirectional pad; push-pull, three-state output. 3.3V tolerant", 6 VCC(I/O) (power) "I/O supply voltage; connect a 0.1uF decoupling capacitor. 1.8V, 2.5V or 3.3V", 7 AD4 (io) "Bit 4 of the address and data bus. Bidirectional pad; push-pull, three-state output. 3.3V tolerant", 8 AD5 (io) "Bit 5 of the address and data bus. Bidirectional pad; push-pull, three-state output. 3.3V tolerant", 9 AD6 (io) "Bit 6 of the address and data bus. Bidirectional pad; push-pull, three-state output. 3.3V tolerant", 10 AD7 (io) "Bit 7 of the address and data bus. Bidirectional pad; push-pull, three-state output. 3.3V tolerant", 11 AD8 (io) "Bit 8 of the address and data bus. Bidirectional pad; push-pull, three-state output. 3.3V tolerant", 12 AD9 (io) "Bit 9 of the address and data bus. Bidirectional pad; push-pull, three-state output. 3.3V tolerant", 13 AD10 (io) "Bit 10 of the address and data bus. Bidirectional pad; push-pull, three-state output. 3.3V tolerant", 14 AD11 (io) "Bit 11 of the address and data bus. Bidirectional pad; push-pull, three-state output. 3.3V tolerant", 15 VCC(I/O) (power) "I/O supply voltage; connect a 0.1uF decoupling capacitor. 1.8V, 2.5V or 3.3V", 16 AD12 (io) "Bit 12 of the address and data bus. Bidirectional pad; push-pull, three-state output. 3.3V tolerant", 17 AD13 (io) "Bit 13 of the address and data bus. Bidirectional pad; push-pull, three-state output. 3.3V tolerant", 18 AD14 (io) "Bit 14 of the address and data bus. Bidirectional pad; push-pull, three-state output. 3.3V tolerant", 19 AD15 (io) "Bit 15 of the address and data bus. Bidirectional pad; push-pull, three-state output. 3.3V tolerant", 20 VCC(1V2) (power) "Core power 1.2V input; for normal operation, this pin must be connected to pin 46. Connect a 0.1uF decoupling capacitor", 21 CS_N/CE_N (in), 22 RD_N/RE_N/OE_N (in), 23 WR_N/WE_N (in), 24 INT (out) "Interrupt output. Push-pull output; 3.3V tolerant", 25 VCC(I/O) (power) "I/O supply voltage; connect a 0.1uF decoupling capacitor. 1.8V, 2.5V or 3.3V", 26 A0 (in) "Bit 0 of the address bus; when not in use, connect to GND. Input; 3.3V tolerant", 27 A1 (in) "Bit 1 of the address bus; when not in use, connect to GND. Input; 3.3V tolerant", 28 A2 (in) "Bit 2 of the address bus; when not in use, connect to GND. Input; 3.3V tolerant", 29 A3 (in) "Bit 3 of the address bus; when not in use, connect to GND. Input; 3.3V tolerant", 30 A4 (in) "Bit 4 of the address bus; when not in use, connect to GND. Input; 3.3V tolerant", 31 A5 (in) "Bit 5 of the address bus; when not in use, connect to GND. Input; 3.3V tolerant", 32 VCC (1V2) (power) "Core power 1.2V input; for normal operation, this pin must be connected to pin 46. Connect a 0.1uF decoupling capacitor.", 33 A6 (in) "Bit 6 of the address bus; when not in use, connect to GND. Input; 3.3V tolerant", 34 A7 (in) "Bit 7 of the address bus; when not in use, connect to GND. Input; 3.3V tolerant", 35 VCC(I/O) (power) "I/O supply voltage; connect a 0.1uF decoupling capacitor. 1.8V, 2.5V or 3.3V", 36 DREQ (out) "DMA request; Push-pull output; 3.3V tolerant", 37 DACK (in) "DMA acknowledge; Internal pull-down. Input; 3.3V tolerant", 38 ALE/ADV_N (in), 39 CLE (in) "Command latch enable. Input; 3.3V tolerant", 40 RESET_N (in) "Chip reset; Internal pull-up. Input; 3.3V tolerant", 41 FREQSEL1 (in) "Input clock frequency selection pin1. Input; 3.3V tolerant", 42 FREQSEL2 (in) "Input clock frequency selection pin2. Input; 3.3V tolerant", 43 AGND (power) "Analog Ground", 44 X1/CLKIN (in) "Crystal oscillator or clock input; 3.3V peak input allowed", 45 X2 "Crystal oscillator output; leave open if an external clock is applied on pin X1/CLKIN", 46 VOUT(1V2) (power) "Internal 1.2V regulator output; connect 4.7uF and 0.1uF decoupling capacitors to this pin.", 47 AGND (power) "Analog Ground", 48 PSW_N (oc) "Port power switch; when not in use, connect to VCC(3V3) through a 10kOhm resistor. Open drain output; 5V tolerant", 49 OC_N (in) "Over current input; when not in use, connect to VCC(3V3) through a 10KOhm resistor. Input; 5V tolerant", 50 RREF (in) "Port reference resistor connection. Connect 12 kOhm±1% resistor between RREF and GND", 51 NC "No connect", 52 DM (io) "Port DM; connect to the D- pin of the USB connector", 53 NC "No connect", 54 DP (io) "Port DP; connect to the D+ pin of the USB connector", 55 AGND (power) "Analog Ground", 56 NC "No connect", 57 VCC(3V3) (power) "Supply 3.3V voltage; Connect 10uF and 0.1uF decoupling capacitors", 58 NC "No connect", 59 AGND (power) "Analog Ground", 60 NC "No connect", 61 VBUS (power) "VBUS discharge. 5V tolerant", 62 CPE0 (in) "Bit 0 to select charging port emulation type", 63 TESTEN (in) "Enable test mode. Internal pull-down. For normal operation leave floating.", 64 CPE1 (in) "Bit 1 to select charging port emulation type"

## FT313HQ-R
designator U?
FT313H Single Chip USB2.0 HS Embedded Host Controller, -40 to +85 degC, 64-pin QFN, Pb-Free, Tape and Reel; Manufacturer: FTDI; PartNumber: FT313HQ-R
footprint QFN-64_N (QFN, 64-Leads, Body 9.1x9.1mm, Pitch 0.5mm, Thermal Pad 3.78x3.78mm, IPC Medium Density)
footprint QFN-64_N (QFN, 64-Leads, Body 9.1x9.1mm, Pitch 0.5mm, Thermal Pad 3.78x3.78mm, IPC High Density)
footprint QFN-64_M (QFN, 64-Leads, Body 9.1x9.1mm, Pitch 0.5mm, Thermal Pad 3.78x3.78mm, IPC Low Density)
pins: 1 AGND (power) "Analog Ground", 2 AD0 (io) "Bit 0 of the address and data bus. Bidirectional pad; push-pull, three-state output. 3.3V tolerant", 3 AD1 (io) "Bit 1 of the address and data bus. Bidirectional pad; push-pull, three-state output. 3.3V tolerant", 4 AD2 (io) "Bit 2 of the address and data bus. Bidirectional pad; push-pull, three-state output. 3.3V tolerant", 5 AD3 (io) "Bit 3 of the address and data bus. Bidirectional pad; push-pull, three-state output. 3.3V tolerant", 6 VCC(I/O) (power) "I/O supply voltage; connect a 0.1uF decoupling capacitor. 1.8V, 2.5V or 3.3V", 7 AD4 (io) "Bit 4 of the address and data bus. Bidirectional pad; push-pull, three-state output. 3.3V tolerant", 8 AD5 (io) "Bit 5 of the address and data bus. Bidirectional pad; push-pull, three-state output. 3.3V tolerant", 9 AD6 (io) "Bit 6 of the address and data bus. Bidirectional pad; push-pull, three-state output. 3.3V tolerant", 10 AD7 (io) "Bit 7 of the address and data bus. Bidirectional pad; push-pull, three-state output. 3.3V tolerant", 11 AD8 (io) "Bit 8 of the address and data bus. Bidirectional pad; push-pull, three-state output. 3.3V tolerant", 12 AD9 (io) "Bit 9 of the address and data bus. Bidirectional pad; push-pull, three-state output. 3.3V tolerant", 13 AD10 (io) "Bit 10 of the address and data bus. Bidirectional pad; push-pull, three-state output. 3.3V tolerant", 14 AD11 (io) "Bit 11 of the address and data bus. Bidirectional pad; push-pull, three-state output. 3.3V tolerant", 15 VCC(I/O) (power) "I/O supply voltage; connect a 0.1uF decoupling capacitor. 1.8V, 2.5V or 3.3V", 16 AD12 (io) "Bit 12 of the address and data bus. Bidirectional pad; push-pull, three-state output. 3.3V tolerant", 17 AD13 (io) "Bit 13 of the address and data bus. Bidirectional pad; push-pull, three-state output. 3.3V tolerant", 18 AD14 (io) "Bit 14 of the address and data bus. Bidirectional pad; push-pull, three-state output. 3.3V tolerant", 19 AD15 (io) "Bit 15 of the address and data bus. Bidirectional pad; push-pull, three-state output. 3.3V tolerant", 20 VCC(1V2) (power) "Core power 1.2V input; for normal operation, this pin must be connected to pin 46. Connect a 0.1uF decoupling capacitor", 21 CS_N/CE_N (in), 22 RD_N/RE_N/OE_N (in), 23 WR_N/WE_N (in), 24 INT (out) "Interrupt output. Push-pull output; 3.3V tolerant", 25 VCC(I/O) (power) "I/O supply voltage; connect a 0.1uF decoupling capacitor. 1.8V, 2.5V or 3.3V", 26 A0 (in) "Bit 0 of the address bus; when not in use, connect to GND. Input; 3.3V tolerant", 27 A1 (in) "Bit 1 of the address bus; when not in use, connect to GND. Input; 3.3V tolerant", 28 A2 (in) "Bit 2 of the address bus; when not in use, connect to GND. Input; 3.3V tolerant", 29 A3 (in) "Bit 3 of the address bus; when not in use, connect to GND. Input; 3.3V tolerant", 30 A4 (in) "Bit 4 of the address bus; when not in use, connect to GND. Input; 3.3V tolerant", 31 A5 (in) "Bit 5 of the address bus; when not in use, connect to GND. Input; 3.3V tolerant", 32 VCC (1V2) (power) "Core power 1.2V input; for normal operation, this pin must be connected to pin 46. Connect a 0.1uF decoupling capacitor.", 33 A6 (in) "Bit 6 of the address bus; when not in use, connect to GND. Input; 3.3V tolerant", 34 A7 (in) "Bit 7 of the address bus; when not in use, connect to GND. Input; 3.3V tolerant", 35 VCC(I/O) (power) "I/O supply voltage; connect a 0.1uF decoupling capacitor. 1.8V, 2.5V or 3.3V", 36 DREQ (out) "DMA request; Push-pull output; 3.3V tolerant", 37 DACK (in) "DMA acknowledge; Internal pull-down. Input; 3.3V tolerant", 38 ALE/ADV_N (in), 39 CLE (in) "Command latch enable. Input; 3.3V tolerant", 40 RESET_N (in) "Chip reset; Internal pull-up. Input; 3.3V tolerant", 41 FREQSEL1 (in) "Input clock frequency selection pin1. Input; 3.3V tolerant", 42 FREQSEL2 (in) "Input clock frequency selection pin2. Input; 3.3V tolerant", 43 AGND (power) "Analog Ground", 44 X1/CLKIN (in) "Crystal oscillator or clock input; 3.3V peak input allowed", 45 X2 "Crystal oscillator output; leave open if an external clock is applied on pin X1/CLKIN", 46 VOUT(1V2) (power) "Internal 1.2V regulator output; connect 4.7uF and 0.1uF decoupling capacitors to this pin.", 47 AGND (power) "Analog Ground", 48 PSW_N (oc) "Port power switch; when not in use, connect to VCC(3V3) through a 10kOhm resistor. Open drain output; 5V tolerant", 49 OC_N (in) "Over current input; when not in use, connect to VCC(3V3) through a 10KOhm resistor. Input; 5V tolerant", 50 RREF (in) "Port reference resistor connection. Connect 12 kOhm±1% resistor between RREF and GND", 51 NC "No connect", 52 DM (io) "Port DM; connect to the D- pin of the USB connector", 53 NC "No connect", 54 DP (io) "Port DP; connect to the D+ pin of the USB connector", 55 AGND (power) "Analog Ground", 56 NC "No connect", 57 VCC(3V3) (power) "Supply 3.3V voltage; Connect 10uF and 0.1uF decoupling capacitors", 58 NC "No connect", 59 AGND (power) "Analog Ground", 60 NC "No connect", 61 VBUS (power) "VBUS discharge. 5V tolerant", 62 CPE0 (in) "Bit 0 to select charging port emulation type", 63 TESTEN (in) "Enable test mode. Internal pull-down. For normal operation leave floating.", 64 CPE1 (in) "Bit 1 to select charging port emulation type", 65 EP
